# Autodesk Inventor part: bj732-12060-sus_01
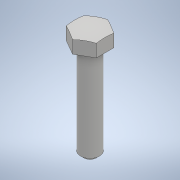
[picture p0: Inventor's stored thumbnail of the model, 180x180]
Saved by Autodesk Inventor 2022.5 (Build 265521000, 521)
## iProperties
Part Number: bj732-12060-sus_01
Material: 一般
Document SubType Name: Modeling
Designer: ImaoCorp
Density: 1 g/cm^3
Appearance: 既定
Author: ImaoCorp
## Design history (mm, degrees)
feature "bj732-12060-sus_01"
node "ソリッド1"
